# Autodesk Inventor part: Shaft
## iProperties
Created: 2011-05
Part Number: Shaft
Material: Steel
Document SubType Name: Modeling
Designer: 904Chiaki
Density: 1 g/cm^3
Author: 904Chiaki
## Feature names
1. Revolution1
2. Chamfer15
3. Chamfer16
4. Chamfer8
5. Chamfer2
6. Hole1
7. Chamfer17
8. Extrusion1
9. Chamfer18
10. Chamfer10
